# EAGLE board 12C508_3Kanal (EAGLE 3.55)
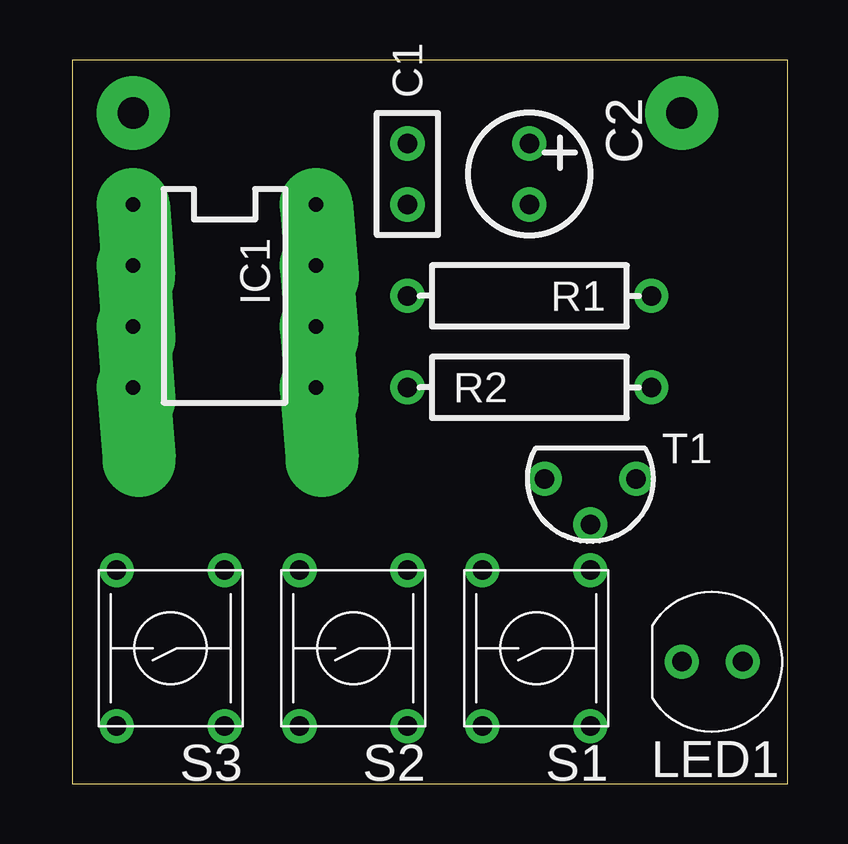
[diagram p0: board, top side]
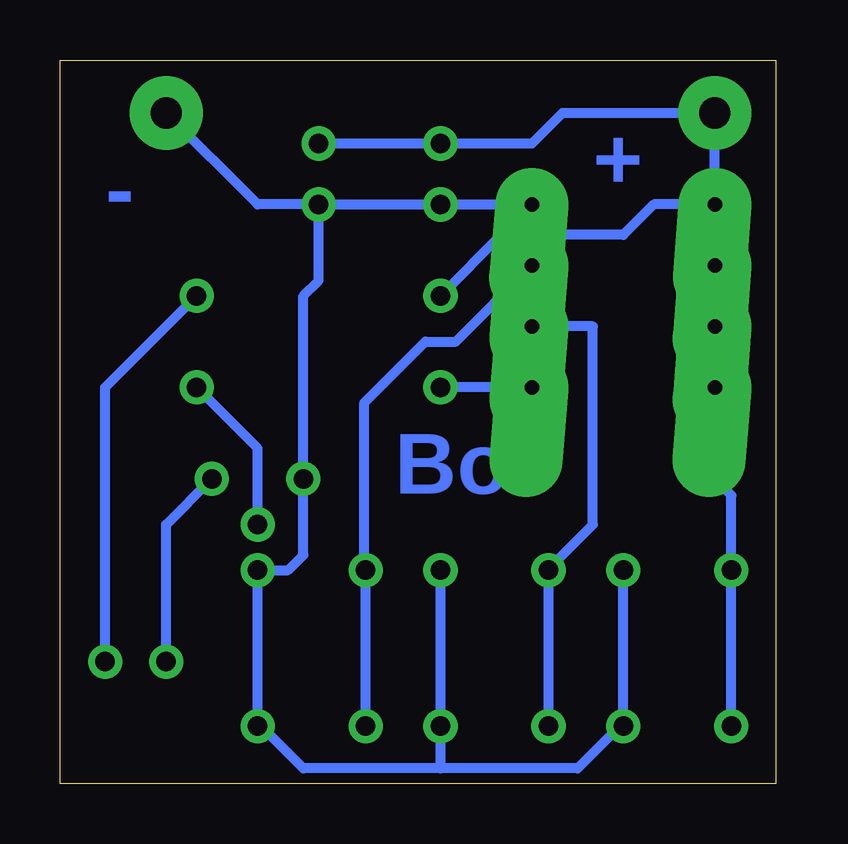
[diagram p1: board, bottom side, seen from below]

Size 29.82 x 30.15 mm. Coordinates in mm from the lower left corner, seen from the top.
Outline: 0,0 29.82,0 29.82,30.15 0,30.15 0,0
Copper layers used: Bottom

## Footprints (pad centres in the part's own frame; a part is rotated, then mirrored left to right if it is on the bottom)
RM2,5 = drill 0.813 pad 1.422 round:  0,0;  2.54,0
KO01 = drill 0.813 pad 1.422 round:  0,0;  2.54,0
L-8B = drill 0.61 pad 3.048 offset:  0,0;  2.54,0;  5.08,0;  7.62,0;  7.62,7.62;  5.08,7.62;  2.54,7.62;  0,7.62
D_5MM = drill 0.813 pad 1.422 round:  -1.27,0;  1.27,0
GEL = drill 1.295 pad 3.048 round:  0,0
S04 = drill 0.813 pad 1.422 round:  0,0;  10.16,0
US = drill 0.813 pad 1.422 round:  0,0;  4.5,0;  4.5,6.5;  0,6.5
92 = drill 0.813 pad 1.422 round:  -0.635,0;  1.27,1.905;  3.175,0

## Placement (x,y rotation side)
C1  C100NK  [RM2,5]  13.97,24.13 90 top
C2  100u  [KO01]  19.05,26.67 270 top
IC1  12C508P  [L-8B]  2.54,24.13 270 top
LED1  LD274  [D_5MM]  26.67,5.08 180 top
N1  +  [GEL]  2.54,27.94 0 top
N2  -  [GEL]  25.4,27.94 0 top
R1  ???  [S04]  24.13,20.32 180 top
R2  1k  [S04]  13.97,16.51 0 top
S1  Code5  [US]  21.59,8.89 180 top
S2  Code6  [US]  13.97,8.89 180 top
S3  Code7  [US]  6.35,8.89 180 top
T1  BC337  [92]  22.86,12.7 180 top

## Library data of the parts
C1 C2 LED1 N1 N2 R1 R2 T1 = holgnorm
IC1 = PIC
S1-S3 = taster1

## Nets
+UB: C1. C2. IC1. N1. R1.
GND: C1. C2. IC1. N2. S1. S2. S3. T1.
N$1: IC1. S1.
N$2: R2. T1.
N$4: LED1. T1.
N$5: LED1. R1.
N$6: IC1. R2.
N$7: IC1. S2.
N$9: IC1. S3.

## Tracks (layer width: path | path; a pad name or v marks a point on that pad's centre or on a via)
+UB
  Bottom 0.406: R1. 11.43,22.86 6.35,22.86 5.08,24.13 2.54,24.13 N1. 8.89,27.94 10.16,26.67 C1. 19.05,26.67
GND
  Bottom 0.406: IC1. 13.97,24.13 C2. | C2. 21.59,24.13 N2. | S3. 6.35,2.54 | 13.97,2.54 S2. | 13.97,2.54 13.97,8.89 | C2. 19.05,20.95 19.68,20.32 T1. 19.68,9.53 20.32,8.89 21.59,8.89 21.59,2.54 | 21.59,2.54 S1. | 21.59,2.54 19.68,0.64 13.97,0.64 | 13.97,0.64 13.97,2.54 | 6.35,2.54 6.35,8.89 | 6.35,2.54 8.26,0.64 13.97,0.64
N$1
  Bottom 0.406: 10.16,21.59 13.34,18.41 14.61,18.41 17.14,15.88 17.14,8.89 | 17.14,8.89 17.09,8.89 | 17.09,2.39 17.09,8.84 17.14,8.89
N$2
  Bottom 0.406: R2. 21.59,13.97 21.59,10.79
N$4
  Bottom 0.406: 23.5,12.7 25.4,10.79 LED1.
N$5
  Bottom 0.406: 24.13,20.32 27.94,16.51 27.94,5.08
N$6
  Bottom 0.406: 10.16,16.51 13.97,16.51
N$7
  Bottom 0.406: 10.16,19.05 7.62,19.05 7.62,10.79 9.53,8.89 9.47,8.89 9.47,2.6 9.53,2.54 9.47,2.48 9.47,2.39
N$9
  Bottom 0.406: 2.54,16.51 2.54,12.7 1.85,12.01 1.85,8.89 1.91,8.89 1.85,8.84 1.85,2.39

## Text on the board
Bottom: + | - | Bot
